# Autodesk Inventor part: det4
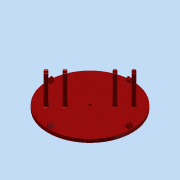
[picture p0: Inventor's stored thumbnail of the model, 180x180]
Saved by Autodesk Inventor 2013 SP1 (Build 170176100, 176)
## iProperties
Created: 2016-04
Part Number: det4
Material: Пластик АБС
Document SubType Name: Обычные детали
Designer: Кравец
Density: 1 g/cm^3
Author: Кравец
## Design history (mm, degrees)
sketch "Эскиз1"
  geometry: L1 (0, 0)-(0, 10.714); L2 (0, 0)-(-50, 0); L3 (-50, 0)-(-50, 4); L4 (-50, 4)-(-1.5, 4); L5 (-1.5, 4)-(-1.5, 1.5); L6 (-1.5, 1.5)-(-0.5, 1.5); L7 (-0.5, 1.5)-(0, 2)
  constraints: 14 end point, 3 parallel, 2 perpendicular, 1 point on line, 1 vertical
  dimensions: "d0" = 100 diameter of L3 L1; "d3" = 3 diameter of L5 L1; "d4" = 2.5 distance of L4.end L5.end; "d5" = 0.5 horizontal distance of L6.end L7.end; "d6" = 1 distance of L5.end L6.end; "d7" = 48.5 distance of L3.end L4.end (derived); "d8" = 4 distance between parallel lines of L2 L4
revolve "Вращение1" sketch "Эскиз1" stored, may be unused: angle "d9" = 90 deg
sketch "Эскиз2"
  geometry: L1 (-2, 49)-(-1, 49); L2 (-1, 49)-(-1, 45); L3 (-1, 45)-(-2, 45); L4 (-2, 45)-(-2, 49); L5 (1, 49)-(2, 49); L6 (2, 49)-(2, 45); L7 (2, 45)-(1, 45); L8 (1, 45)-(1, 49); C1 r 1.5 at (0, 0) reference; C2 r 50 at (0, 0) reference
  constraints: 16 end point, 4 parallel, 2 equal length, 2 horizontal, 2 perpendicular, 1 collinear
  dimensions: "d10" = 2 distance between parallel lines of L8 L2; "d12" = 1 distance of L1.start L1.end; "d13" = 1 distance edge to line of C2 L1; "d14" = 4 distance of L3.end L1.start; "d15" = 1 distance from line of C1.centre L2 (= 0.5 x d10)
extrude "Выдавливание1" join sketch "Эскиз2" distance "d16" = 5; taper "d17" = 0 deg
fillet "Сопряжение1" dims "d18" = 2
fillet "Сопряжение2" dims "d19" = 2
hole "Отверстие1" diameter "d22" = 1.5; stored, may be unused: countersink angle "d26" = 90 deg, drill point angle "d28" = 118 deg; dims "d20" = 10, "d21" = 10, "d23" = 6, "d24" = 4, "d25" = 2, "d27" = 8
pattern_circular "Круговой массив1" dims "d30" = 360 deg
sketch "Эскиз3"
  geometry: L1 (3, -86)-(3, -92.96) reference; L2 (-26.224, -65.274)-(-21.274, -70.224); L3 (-21.274, -70.224)-(-24.102, -73.052); L4 (-24.102, -73.052)-(-29.052, -68.102); L5 (-29.052, -68.102)-(-26.224, -65.274); L6 (-17.738, -56.789)-(-12.789, -61.738); L7 (-12.789, -61.738)-(-9.96, -58.91); L8 (-9.96, -58.91)-(-14.91, -53.96); L9 (-14.91, -53.96)-(-17.738, -56.789); L10 (1, -43)-(1, -65.747); L11 (1, -43)-(-4.399, -48.399); L12 (-12.435, -56.435)-(-15.263, -59.263); C1 r 1.5 at (1, -43) reference; A1 r 50 centre (1, -43) between (50.99, -44) and (50.99, -42) reference
  constraints: 22 end point, 5 parallel, 4 perpendicular, 3 equal length, 2 collinear, 2 midpoint, 1 point on line
  dimensions: "d32" = 45 deg angle of L10 L11; "d33" = 4 distance of L8.end L6.start; "d35" = 12 distance between parallel lines of L6 L2; "d36" = 23 distance from line of A1.centre L6; "d37" = 7 distance of L7.end L8.end
extrude "Выдавливание2" join sketch "Эскиз3" distance "d38" = 37; taper "d39" = 0 deg
sketch "Эскиз4"
  geometry: L1 (0, 37)-(7, 37) reference; L2 (0, 37)-(0, 0) reference; L3 (7, 0)-(0, 0) reference; L4 (7, 37)-(7, 0) reference; L5 (2.25, 3.171)-(0, 1.171); L6 (4.75, 3.171)-(7, 1.171); L7 (2.25, 3.171)-(4.75, 3.171); L8 (0, 1.171)-(7, 1.171); A1 r 1.5 centre (3.5, 4) between (2.25, 3.171) and (4.75, 3.171); 1 further point
  constraints: 8 end point, 2 point on circle, 2 point on line, 1 centre point, 1 equal length, 1 horizontal, 1 parallel
  dimensions: "d40" = 3 diameter of A1; "d42" = 33 distance from line of L1 A1.centre; "d43" = 2.5 distance of L6.start L5.start; "d44" = 2 distance between parallel lines of L8 L7
extrude "Выдавливание3" cut sketch "Эскиз4" distance "d45" = 37; taper "d46" = 0 deg
fillet "Сопряжение3" dims "d47" = 1
fillet "Сопряжение4" dims "d48" = 0.2
fillet "Сопряжение5" dims "d49" = 1, "d50" = 1
pattern_circular "Круговой массив2" dims "d52" = 360 deg
node "Твердое тело1"
other parameters: "Толщина" = 0.5, "Поправка" = 4.4, "Радиус_гибки" = 0.5 (= Толщина), "Ширина_просечки" = 0.5 (= Толщина), "Глубина_просечки" = 0.25 (= 0.5 x Толщина), "Размер_просечки" = 2 (= 4 x Толщина), "Зазор_стыка" = 0.01, "Мин_остаток" = 1 (= 2 x Толщина), "Радиус_перехода" = 0.5 (= Радиус_гибки), "Радиус_Якоби" = 0.5 (= Толщина), "Размер_зазора" = 0.5 (= Толщина)
